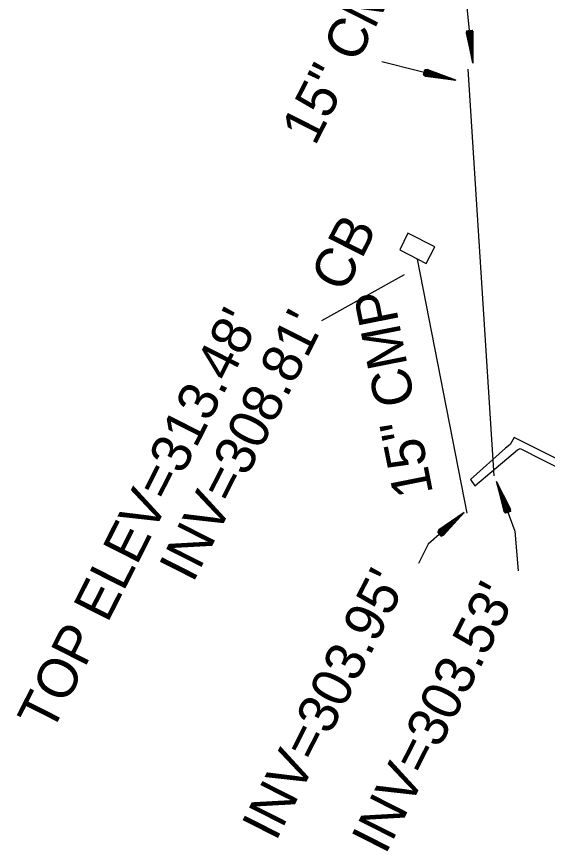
# Model space of a CAD drawing. Extents: x 1975859 to 1978323, y 778892 to 782836.
# Drawn here: x 1977901.5 to 1977955.1, y 782587.9 to 782672.2 of the extents above; entities that cross this region are included whole.
import ezdxf

# ---------------------------------------------------------------- set-up
doc = ezdxf.new("R2010")
doc.units = 0
for name, color, linetype in [('Exist Structure Major Bridge WW', 7, 'Continuous'), ('Exist Structure Minor Catch Basin', 7, 'Continuous'), ('Exist Structure Minor Catch Basin Text', 7, 'Continuous'), ('Exist Structure Minor Catch Basin Top Elevation', 7, 'Continuous'), ('Exist Structure Minor Pipes CMP 15 Inch', 7, 'Continuous'), ('Exist Structure Minor Pipes CMP 15 Inch Invert', 7, 'Continuous'), ('Exist Structure Minor Pipes CMP 15 Inch SizeText', 7, 'Continuous')]:
    doc.layers.add(name, color=color, linetype=linetype)

msp = doc.modelspace()

# ---------------------------------------------------------------- linework, layer by layer
at = {"layer": 'Exist Structure Major Bridge WW'}
for p, q in [((1977951.778, 782629.725), (1977951.387, 782629.02)), ((1977974.789, 782618.155), (1977951.778, 782629.725)), ((1977947.355, 782625.475), (1977950.906, 782628.652)), ((1977951.387, 782629.02), (1977950.906, 782628.652)), ((1977952.103, 782628.479), (1977952.38, 782628.608)), ((1977952.38, 782628.608), (1977972.779, 782618.373)), ((1977947.795, 782624.859), (1977952.103, 782628.479)), ((1977947.355, 782625.475), (1977947.795, 782624.859))]:
    msp.add_line(p, q, dxfattribs=at)
at = {"layer": 'Exist Structure Minor Catch Basin'}
msp.add_line((1977940.23, 782648.67), (1977942.881, 782647.312), dxfattribs=at)
msp.add_lwpolyline([(1977942.881, 782647.312), (1977943.764, 782648.987), (1977941.041, 782650.373), (1977940.23, 782648.67)], dxfattribs=at)
at = {"layer": 'Exist Structure Minor Pipes CMP 15 Inch'}
for p, q in [((1977949.752, 782625.857), (1977947.122, 782666.914)), ((1977941.994, 782647.726), (1977947, 782622.092))]:
    msp.add_line(p, q, dxfattribs=at)
at = {"layer": 'Exist Structure Minor Pipes CMP 15 Inch Invert'}
for p, q in [((1977947.621, 782667.54), (1977946.224, 782680.79)), ((1977947.008, 782670.81), (1977947.539, 782670.866)), ((1977947.307, 782670.52), (1977947.062, 782670.77)), ((1977947.307, 782670.52), (1977947.11, 782670.821)), ((1977947.307, 782670.52), (1977947.216, 782670.832)), ((1977947.307, 782670.52), (1977947.42, 782670.852)), ((1977947.307, 782670.52), (1977947.332, 782670.846)), ((1977947.495, 782670.816), (1977947.307, 782670.52)), ((1977938.399, 782667.686), (1977945.895, 782665.802)), ((1977942.613, 782666.352), (1977942.744, 782666.869)), ((1977942.989, 782666.532), (1977942.639, 782666.451)), ((1977942.989, 782666.532), (1977942.664, 782666.554)), ((1977942.989, 782666.532), (1977942.67, 782666.388)), ((1977942.989, 782666.532), (1977942.691, 782666.668)), ((1977942.989, 782666.532), (1977942.716, 782666.753)), ((1977942.776, 782666.811), (1977942.989, 782666.532)), ((1977950.013, 782625.288), (1977951.859, 782620.259)), ((1977946.737, 782622.159), (1977943.086, 782618.958)), ((1977951.406, 782622.266), (1977950.906, 782622.083)), ((1977950.935, 782622.142), (1977951.046, 782622.475)), ((1977951.046, 782622.475), (1977951.017, 782622.126)), ((1977951.046, 782622.475), (1977951.345, 782622.292)), ((1977951.046, 782622.475), (1977951.31, 782622.231)), ((1977951.046, 782622.475), (1977951.21, 782622.194)), ((1977951.046, 782622.475), (1977951.102, 782622.152)), ((1977944.133, 782620.167), (1977944.484, 782620.183)), ((1977944.484, 782620.183), (1977944.147, 782620.084)), ((1977944.484, 782620.183), (1977944.203, 782620.015)), ((1977944.484, 782620.183), (1977944.281, 782619.929)), ((1977944.484, 782620.183), (1977944.351, 782619.849)), ((1977944.484, 782620.183), (1977944.421, 782619.839)), ((1977951.859, 782620.259), (1977952.196, 782616.256)), ((1977944.419, 782619.772), (1977944.067, 782620.173)), ((1977943.086, 782618.958), (1977942.103, 782617.018))]:
    msp.add_line(p, q, dxfattribs=at)
for points in [[(1977947.008, 782670.81), (1977946.941, 782670.572), (1977947.621, 782667.54), (1977947.654, 782670.647), (1977947.539, 782670.866)], [(1977947.596, 782670.756), (1977947.621, 782667.54), (1977946.975, 782670.691)], [(1977947.083, 782670.664), (1977947.621, 782667.54), (1977947.008, 782670.81), (1977947.062, 782670.77), (1977947.083, 782670.664), (1977947.307, 782670.52), (1977947.5, 782670.708), (1977947.495, 782670.816), (1977947.539, 782670.866), (1977947.621, 782667.54), (1977947.5, 782670.708)], [(1977947.613, 782667.714), (1977947.611, 782667.633), (1977947.589, 782667.725), (1977947.573, 782667.817), (1977947.601, 782667.726), (1977947.61, 782667.807), (1977947.606, 782667.902), (1977947.592, 782667.82), (1977947.558, 782667.91), (1977947.542, 782668.002), (1977947.582, 782667.912), (1977947.603, 782667.995), (1977947.599, 782668.088), (1977947.572, 782668.006), (1977947.526, 782668.093), (1977947.51, 782668.186), (1977947.562, 782668.099), (1977947.596, 782668.181), (1977947.592, 782668.275), (1977947.552, 782668.192), (1977947.494, 782668.279), (1977947.478, 782668.37), (1977947.542, 782668.285), (1977947.588, 782668.368), (1977947.585, 782668.462), (1977947.533, 782668.378), (1977947.463, 782668.463), (1977947.446, 782668.555), (1977947.523, 782668.471), (1977947.581, 782668.556), (1977947.578, 782668.649), (1977947.513, 782668.564), (1977947.431, 782668.647), (1977947.415, 782668.74), (1977947.503, 782668.657), (1977947.574, 782668.743), (1977947.571, 782668.836), (1977947.493, 782668.751), (1977947.399, 782668.832), (1977947.383, 782668.924), (1977947.484, 782668.844), (1977947.567, 782668.93), (1977947.564, 782669.024), (1977947.474, 782668.937), (1977947.367, 782669.016), (1977947.351, 782669.109), (1977947.464, 782669.03), (1977947.56, 782669.117), (1977947.556, 782669.211), (1977947.454, 782669.123), (1977947.335, 782669.201), (1977947.319, 782669.293), (1977947.444, 782669.216), (1977947.553, 782669.304), (1977947.549, 782669.398), (1977947.434, 782669.309), (1977947.304, 782669.385), (1977947.288, 782669.478), (1977947.425, 782669.402), (1977947.546, 782669.491), (1977947.542, 782669.585), (1977947.415, 782669.495), (1977947.272, 782669.57), (1977947.256, 782669.662), (1977947.405, 782669.589), (1977947.538, 782669.679), (1977947.535, 782669.772), (1977947.395, 782669.682), (1977947.24, 782669.755), (1977947.224, 782669.846), (1977947.377, 782669.774), (1977947.532, 782669.865), (1977947.528, 782669.959), (1977947.376, 782669.868), (1977947.208, 782669.939), (1977947.192, 782670.031), (1977947.366, 782669.961), (1977947.525, 782670.052), (1977947.521, 782670.146), (1977947.356, 782670.054), (1977947.177, 782670.124), (1977947.161, 782670.216), (1977947.346, 782670.147), (1977947.518, 782670.24), (1977947.514, 782670.334), (1977947.336, 782670.241), (1977947.144, 782670.308), (1977947.129, 782670.4), (1977947.326, 782670.334), (1977947.51, 782670.427), (1977947.507, 782670.521), (1977947.317, 782670.427), (1977947.113, 782670.493), (1977947.097, 782670.585), (1977947.307, 782670.52), (1977947.503, 782670.614)], [(1977942.613, 782666.352), (1977942.815, 782666.206), (1977945.895, 782665.802), (1977942.989, 782666.902), (1977942.744, 782666.869)], [(1977942.777, 782666.372), (1977945.895, 782665.802), (1977942.613, 782666.352), (1977942.67, 782666.388), (1977942.777, 782666.372), (1977942.989, 782666.532), (1977942.879, 782666.778), (1977942.776, 782666.811), (1977942.744, 782666.869), (1977945.895, 782665.802), (1977942.879, 782666.778)], [(1977942.867, 782666.886), (1977945.895, 782665.802), (1977942.715, 782666.28)], [(1977945.729, 782665.855), (1977945.804, 782665.825), (1977945.711, 782665.836), (1977945.619, 782665.853), (1977945.713, 782665.848), (1977945.64, 782665.884), (1977945.551, 782665.913), (1977945.622, 782665.871), (1977945.526, 782665.87), (1977945.434, 782665.887), (1977945.532, 782665.894), (1977945.462, 782665.942), (1977945.373, 782665.97), (1977945.441, 782665.916), (1977945.343, 782665.903), (1977945.25, 782665.92), (1977945.35, 782665.939), (1977945.284, 782665.999), (1977945.194, 782666.028), (1977945.259, 782665.962), (1977945.158, 782665.937), (1977945.066, 782665.954), (1977945.168, 782665.985), (1977945.106, 782666.057), (1977945.017, 782666.086), (1977945.078, 782666.008), (1977944.974, 782665.971), (1977944.882, 782665.988), (1977944.987, 782666.03), (1977944.927, 782666.114), (1977944.839, 782666.144), (1977944.896, 782666.053), (1977944.79, 782666.005), (1977944.698, 782666.022), (1977944.805, 782666.076), (1977944.749, 782666.172), (1977944.66, 782666.201), (1977944.714, 782666.099), (1977944.606, 782666.038), (1977944.514, 782666.055), (1977944.623, 782666.122), (1977944.571, 782666.23), (1977944.482, 782666.259), (1977944.533, 782666.145), (1977944.421, 782666.072), (1977944.329, 782666.089), (1977944.442, 782666.167), (1977944.393, 782666.288), (1977944.304, 782666.316), (1977944.351, 782666.19), (1977944.237, 782666.105), (1977944.145, 782666.122), (1977944.261, 782666.213), (1977944.215, 782666.345), (1977944.126, 782666.374), (1977944.17, 782666.236), (1977944.053, 782666.139), (1977943.961, 782666.156), (1977944.079, 782666.258), (1977944.037, 782666.403), (1977943.948, 782666.432), (1977943.988, 782666.282), (1977943.869, 782666.172), (1977943.777, 782666.189), (1977943.897, 782666.304), (1977943.859, 782666.461), (1977943.77, 782666.49), (1977943.806, 782666.327), (1977943.684, 782666.206), (1977943.593, 782666.223), (1977943.714, 782666.341), (1977943.681, 782666.518), (1977943.592, 782666.547), (1977943.625, 782666.373), (1977943.501, 782666.24), (1977943.409, 782666.257), (1977943.534, 782666.395), (1977943.503, 782666.576), (1977943.413, 782666.605), (1977943.443, 782666.419), (1977943.316, 782666.274), (1977943.224, 782666.291), (1977943.353, 782666.441), (1977943.325, 782666.634), (1977943.235, 782666.662), (1977943.262, 782666.464), (1977943.132, 782666.307), (1977943.04, 782666.324), (1977943.171, 782666.487), (1977943.147, 782666.691), (1977943.057, 782666.72), (1977943.08, 782666.51), (1977942.948, 782666.341), (1977942.856, 782666.358), (1977942.989, 782666.532), (1977942.968, 782666.749)], [(1977940.677, 782646.171), (1977932.325, 782641.498)], [(1977951.298, 782622.39), (1977950.013, 782625.288), (1977951.406, 782622.266), (1977951.345, 782622.292), (1977951.298, 782622.39), (1977951.046, 782622.475), (1977950.905, 782622.246), (1977950.935, 782622.142), (1977950.906, 782622.083), (1977950.013, 782625.288), (1977950.905, 782622.246)], [(1977951.406, 782622.266), (1977951.413, 782622.514), (1977950.013, 782625.288), (1977950.74, 782622.267), (1977950.906, 782622.083)], [(1977950.823, 782622.176), (1977950.013, 782625.288), (1977951.409, 782622.391)], [(1977950.063, 782625.122), (1977950.046, 782625.2), (1977950.089, 782625.117), (1977950.127, 782625.031), (1977950.078, 782625.112), (1977950.089, 782625.032), (1977950.116, 782624.941), (1977950.11, 782625.024), (1977950.165, 782624.945), (1977950.203, 782624.86), (1977950.142, 782624.937), (1977950.142, 782624.851), (1977950.168, 782624.762), (1977950.174, 782624.848), (1977950.241, 782624.775), (1977950.279, 782624.689), (1977950.207, 782624.761), (1977950.194, 782624.672), (1977950.221, 782624.582), (1977950.239, 782624.672), (1977950.317, 782624.603), (1977950.355, 782624.518), (1977950.272, 782624.584), (1977950.247, 782624.493), (1977950.273, 782624.403), (1977950.304, 782624.497), (1977950.392, 782624.432), (1977950.431, 782624.346), (1977950.336, 782624.409), (1977950.3, 782624.313), (1977950.326, 782624.223), (1977950.368, 782624.321), (1977950.468, 782624.261), (1977950.506, 782624.175), (1977950.4, 782624.233), (1977950.353, 782624.133), (1977950.379, 782624.043), (1977950.433, 782624.145), (1977950.544, 782624.09), (1977950.582, 782624.004), (1977950.465, 782624.057), (1977950.405, 782623.953), (1977950.431, 782623.863), (1977950.497, 782623.97), (1977950.62, 782623.919), (1977950.658, 782623.833), (1977950.529, 782623.882), (1977950.457, 782623.773), (1977950.484, 782623.684), (1977950.562, 782623.794), (1977950.696, 782623.747), (1977950.734, 782623.662), (1977950.594, 782623.706), (1977950.51, 782623.594), (1977950.536, 782623.504), (1977950.626, 782623.618), (1977950.772, 782623.576), (1977950.81, 782623.49), (1977950.658, 782623.53), (1977950.562, 782623.414), (1977950.589, 782623.324), (1977950.691, 782623.442), (1977950.848, 782623.405), (1977950.886, 782623.319), (1977950.723, 782623.354), (1977950.616, 782623.234), (1977950.642, 782623.145), (1977950.755, 782623.266), (1977950.924, 782623.233), (1977950.961, 782623.148), (1977950.796, 782623.181), (1977950.668, 782623.055), (1977950.694, 782622.965), (1977950.82, 782623.091), (1977950.999, 782623.062), (1977951.037, 782622.977), (1977950.852, 782623.003), (1977950.72, 782622.875), (1977950.747, 782622.785), (1977950.884, 782622.915), (1977951.075, 782622.891), (1977951.113, 782622.806), (1977950.917, 782622.827), (1977950.773, 782622.695), (1977950.799, 782622.606), (1977950.949, 782622.739), (1977951.152, 782622.72), (1977951.189, 782622.634), (1977950.981, 782622.651), (1977950.826, 782622.516), (1977950.852, 782622.426), (1977951.013, 782622.563), (1977951.227, 782622.549), (1977951.265, 782622.463), (1977951.046, 782622.475), (1977950.879, 782622.336)], [(1977944.495, 782619.917), (1977946.737, 782622.159), (1977944.419, 782619.772), (1977944.421, 782619.839), (1977944.495, 782619.917), (1977944.484, 782620.183), (1977944.219, 782620.232), (1977944.133, 782620.167), (1977944.067, 782620.173), (1977946.737, 782622.159), (1977944.219, 782620.232)], [(1977944.419, 782619.772), (1977944.653, 782619.854), (1977946.737, 782622.159), (1977944.18, 782620.394), (1977944.067, 782620.173)], [(1977944.124, 782620.284), (1977946.737, 782622.159), (1977944.536, 782619.814)], [(1977946.599, 782622.052), (1977946.666, 782622.096), (1977946.604, 782622.026), (1977946.538, 782621.96), (1977946.596, 782622.035), (1977946.525, 782621.995), (1977946.45, 782621.938), (1977946.525, 782621.973), (1977946.471, 782621.894), (1977946.405, 782621.828), (1977946.455, 782621.912), (1977946.376, 782621.882), (1977946.302, 782621.824), (1977946.385, 782621.85), (1977946.34, 782621.761), (1977946.273, 782621.695), (1977946.314, 782621.788), (1977946.228, 782621.768), (1977946.153, 782621.711), (1977946.244, 782621.726), (1977946.207, 782621.629), (1977946.141, 782621.563), (1977946.173, 782621.665), (1977946.079, 782621.654), (1977946.005, 782621.597), (1977946.103, 782621.603), (1977946.075, 782621.497), (1977946.008, 782621.431), (1977946.033, 782621.541), (1977945.93, 782621.54), (1977945.855, 782621.483), (1977945.962, 782621.48), (1977945.942, 782621.364), (1977945.876, 782621.298), (1977945.892, 782621.418), (1977945.781, 782621.426), (1977945.707, 782621.37), (1977945.821, 782621.356), (1977945.809, 782621.232), (1977945.743, 782621.166), (1977945.751, 782621.294), (1977945.633, 782621.313), (1977945.558, 782621.256), (1977945.681, 782621.233), (1977945.677, 782621.1), (1977945.611, 782621.033), (1977945.61, 782621.171), (1977945.483, 782621.199), (1977945.409, 782621.142), (1977945.54, 782621.109), (1977945.545, 782620.967), (1977945.478, 782620.901), (1977945.47, 782621.047), (1977945.335, 782621.085), (1977945.261, 782621.029), (1977945.399, 782620.986), (1977945.413, 782620.835), (1977945.346, 782620.768), (1977945.329, 782620.924), (1977945.186, 782620.972), (1977945.112, 782620.915), (1977945.258, 782620.862), (1977945.28, 782620.702), (1977945.214, 782620.636), (1977945.188, 782620.801), (1977945.038, 782620.858), (1977944.963, 782620.801), (1977945.117, 782620.739), (1977945.147, 782620.57), (1977945.082, 782620.504), (1977945.053, 782620.671), (1977944.889, 782620.744), (1977944.814, 782620.688), (1977944.977, 782620.615), (1977945.015, 782620.438), (1977944.949, 782620.372), (1977944.906, 782620.554), (1977944.74, 782620.631), (1977944.666, 782620.573), (1977944.836, 782620.492), (1977944.883, 782620.305), (1977944.816, 782620.239), (1977944.765, 782620.43), (1977944.591, 782620.517), (1977944.517, 782620.459), (1977944.695, 782620.368), (1977944.75, 782620.172), (1977944.684, 782620.107), (1977944.625, 782620.307), (1977944.443, 782620.403), (1977944.368, 782620.346), (1977944.554, 782620.245), (1977944.618, 782620.04), (1977944.551, 782619.974), (1977944.484, 782620.183), (1977944.294, 782620.289)]]:
    msp.add_lwpolyline(points, dxfattribs=at)

# ---------------------------------------------------------------- texts
at = {"layer": 'Exist Structure Minor Catch Basin Text'}
msp.add_text('CB', height=4, rotation=63.11985, dxfattribs=at).set_placement((1977934.627, 782644.206))
at = {"layer": 'Exist Structure Minor Catch Basin Top Elevation'}
msp.add_text("TOP ELEV=313.48'", height=4, rotation=63.11985, dxfattribs=at).set_placement((1977905.05, 782599.772))
at = {"layer": 'Exist Structure Minor Pipes CMP 15 Inch Invert'}
for s, p in [("INV=308.81'", (1977919.335, 782614.948)), ("INV=303.95'", (1977927.7, 782588.849)), ("INV=303.53'", (1977938.773, 782587.505))]:
    msp.add_text(s, height=4, rotation=63.11985, dxfattribs=at).set_placement(p)
at = {"layer": 'Exist Structure Minor Pipes CMP 15 Inch SizeText'}
for rotation, p in [(63.11985, (1977931.67, 782659.086)), (101.28361, (1977943.606, 782624.115))]:
    msp.add_text('15" CMP', height=4, rotation=rotation, dxfattribs=at).set_placement(p)

doc.saveas('drawing.dxf')
